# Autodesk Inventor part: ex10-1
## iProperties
Author: Administrator
Created: 2001-10
Part Number: ex10-1
Document SubType Name: Modeling
Designer: Administrator
Control State: 0
Master: False
Checked Out: False
PropertySet Name: Design Tracking Control
Shininess: 64.0
Angle Display Precision: 2
Document Length Units: 11272
Document Angle Units: 11286
Document Time Units: 11279
Document Mass Units: 11290
Document Length Units Precision: 3
Document Angle Units Precision: 2
Compacted: True
PropertySet Name: _Private Model Information
Density: 0.0
Volumn: 0.0
Area: 0.0
PropertySet Name: Model Information
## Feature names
1. Extrusion1
2. Hole1
3. Hole2
4. Fillet1
